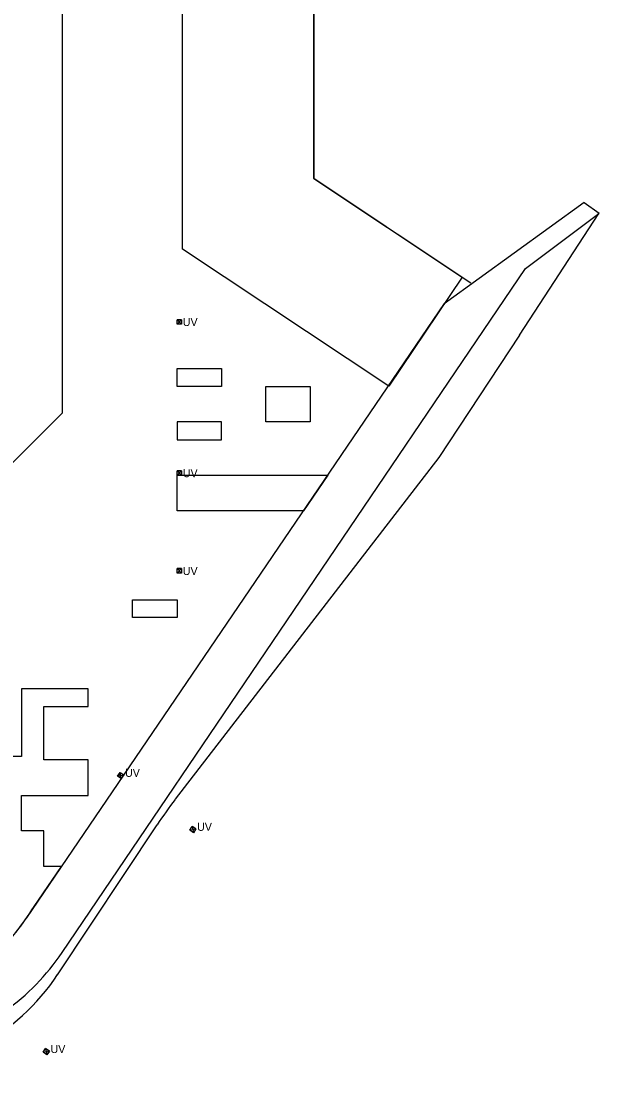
# Model space of a CAD drawing. Extents: x -264222 to -263676, y -1242344 to -1242060.
# Drawn here: x -263799.5 to -263734.5, y -1242301.5 to -1242183.3 of the extents above; entities that cross this region are included whole.
import ezdxf

# ---------------------------------------------------------------- set-up
doc = ezdxf.new("R2010")
doc.units = 0
doc.layers.add('PROJEKT_DRS_OBRUBNIKY_KOMUNIKACIE', color=7, linetype='Continuous')
doc.layers.add('PROJEKT_DRS_UV_STAVBY', color=7, linetype='Continuous')

msp = doc.modelspace()

# ---------------------------------------------------------------- linework, layer by layer
at = {"layer": 'PROJEKT_DRS_OBRUBNIKY_KOMUNIKACIE'}
for p, q in [((-263766.58, -1242201.01), (-263766.58, -1242144.85)), ((-263758.42, -1242206.43), (-263766.58, -1242201.01)), ((-263736.13, -1242203.7), (-263751.89, -1242215.1)), ((-263736.13, -1242203.7), (-263734.47, -1242204.91)), ((-263742.74, -1242211.14), (-263734.49, -1242204.94)), ((-263757.19, -1242207.25), (-263758.42, -1242206.43)), ((-263748.89, -1242212.77), (-263757.19, -1242207.25)), ((-263794.9, -1242288.03), (-263742.74, -1242211.14)), ((-263798.9, -1242284.13), (-263751.86, -1242215.08)), ((-263751.89, -1242215.1), (-263751.89, -1242215.1)), ((-263743.42, -1242218.61), (-263752.52, -1242232.37)), ((-263781.97, -1242228.38), (-263781.97, -1242230.38)), ((-263776.97, -1242228.38), (-263781.97, -1242228.38)), ((-263776.97, -1242230.38), (-263776.97, -1242228.38)), ((-263781.97, -1242230.38), (-263776.97, -1242230.38)), ((-263752.52, -1242232.37), (-263782.17, -1242270.82)), ((-263781.97, -1242234.38), (-263771.97, -1242234.38)), ((-263781.97, -1242238.38), (-263781.97, -1242234.38)), ((-263771.97, -1242234.38), (-263765.01, -1242234.38)), ((-263765.01, -1242234.38), (-263767.74, -1242238.38)), ((-263771.97, -1242238.38), (-263781.97, -1242238.38)), ((-263767.74, -1242238.38), (-263771.97, -1242238.38)), ((-263795.42, -1242290.54), (-263784.21, -1242273.68))]:
    msp.add_line(p, q, dxfattribs=at)
for points in [[(-263766.58, -1242083.48), (-263766.58, -1242201.01), (-263749.88, -1242212.11), (-263758.15, -1242224.37), (-263781.36, -1242208.94), (-263781.37, -1242084.9), (-263766.58, -1242083.48)], [(-263794.89, -1242227.38), (-263808.97, -1242241.46), (-263894.97, -1242241.46), (-263909.04, -1242227.38), (-263909.04, -1242196.33), (-263914.14, -1242196.33), (-263914.14, -1242132.43), (-263909.04, -1242132.43), (-263909.04, -1242101.38), (-263894.97, -1242087.31), (-263808.97, -1242087.31), (-263794.89, -1242101.38), (-263794.89, -1242227.38)], [(-263743.42, -1242218.61), (-263734.49, -1242204.94), (-263734.47, -1242204.91)], [(-263781.97, -1242222.38), (-263776.97, -1242222.38), (-263776.97, -1242224.38), (-263781.97, -1242224.38), (-263781.97, -1242222.38)], [(-263771.97, -1242224.38), (-263766.97, -1242224.38), (-263766.97, -1242228.38), (-263771.97, -1242228.38), (-263771.97, -1242224.38)], [(-263786.97, -1242248.38), (-263781.97, -1242248.38), (-263781.97, -1242250.38), (-263786.97, -1242250.38), (-263786.97, -1242248.38)], [(-263798.06, -1242282.88), (-263794.99, -1242278.38), (-263796.97, -1242278.38), (-263796.97, -1242274.38), (-263799.47, -1242274.38), (-263799.47, -1242270.38), (-263791.97, -1242270.38), (-263791.97, -1242266.38), (-263796.97, -1242266.38), (-263796.97, -1242260.38), (-263791.97, -1242260.38), (-263791.97, -1242258.38), (-263799.47, -1242258.38), (-263799.47, -1242265.99), (-263802.07, -1242265.99)]]:
    msp.add_lwpolyline(points, dxfattribs=at)
for centre, radius, start, end in [((-263742.57, -1242301.35), 50, 142.3688, 146.3992), ((-263821.81, -1242268.3), 27.86, 313.7192, 328.4502), ((-263820.07, -1242269.91), 25.5, 305.2702, 326.1165), ((-263816.07, -1242273.82), 25.5, 305.2702, 326.1165), ((-263815.82, -1242276.98), 24.5, 270, 326.3992)]:
    msp.add_arc(centre, radius, start, end, dxfattribs=at)
at = {"layer": 'PROJEKT_DRS_UV_STAVBY'}
for points in [[(-263781.97, -1242217.38), (-263781.97, -1242216.88), (-263781.47, -1242216.88), (-263781.47, -1242217.38), (-263781.97, -1242217.38), (-263781.47, -1242216.88), (-263781.97, -1242216.88), (-263781.47, -1242217.38)], [(-263781.97, -1242234.38), (-263781.97, -1242233.88), (-263781.47, -1242233.88), (-263781.47, -1242234.38), (-263781.97, -1242234.38), (-263781.47, -1242233.88), (-263781.97, -1242233.88), (-263781.47, -1242234.38)], [(-263781.97, -1242245.38), (-263781.97, -1242244.88), (-263781.47, -1242244.88), (-263781.47, -1242245.38), (-263781.97, -1242245.38), (-263781.47, -1242244.88), (-263781.97, -1242244.88), (-263781.47, -1242245.38)], [(-263788.25, -1242268.49), (-263788.66, -1242268.2), (-263788.37, -1242267.79), (-263787.96, -1242268.08), (-263788.25, -1242268.49), (-263788.37, -1242267.79), (-263788.66, -1242268.2), (-263787.96, -1242268.08)], [(-263780.55, -1242274.29), (-263780.27, -1242273.87), (-263779.85, -1242274.15), (-263780.13, -1242274.57), (-263780.55, -1242274.29), (-263779.85, -1242274.15), (-263780.27, -1242273.87), (-263780.13, -1242274.57)], [(-263797.05, -1242299.27), (-263796.77, -1242298.86), (-263796.35, -1242299.13), (-263796.63, -1242299.55), (-263797.05, -1242299.27), (-263796.35, -1242299.13), (-263796.77, -1242298.86), (-263796.63, -1242299.55)]]:
    msp.add_lwpolyline(points, dxfattribs=at)

# ---------------------------------------------------------------- texts
for p in [(-263781.33, -1242217.59), (-263781.33, -1242234.59), (-263781.33, -1242245.59), (-263787.83, -1242268.29), (-263779.72, -1242274.36), (-263796.22, -1242299.35)]:
    msp.add_text('UV', height=0.9, rotation=359.8587, dxfattribs=at).set_placement(p)

doc.saveas('drawing.dxf')
